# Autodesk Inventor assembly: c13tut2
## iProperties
Created: 2002-04
Part Number: c13tut2
Document SubType Name: Assembly
Control State: 0
Master: False
Checked Out: False
PropertySet Name: Design Tracking Control
Shininess: 64.0
Angle Display Precision: 2
Document Length Units: 11269
Document Angle Units: 11283
Document Time Units: 11279
Document Mass Units: 11290
Document Length Units Precision: 3
Document Angle Units Precision: 2
Compacted: False
PropertySet Name: _Private Model Information
Density: 0.0
Volumn: 0.0
Area: 0.0
PropertySet Name: Model Information
